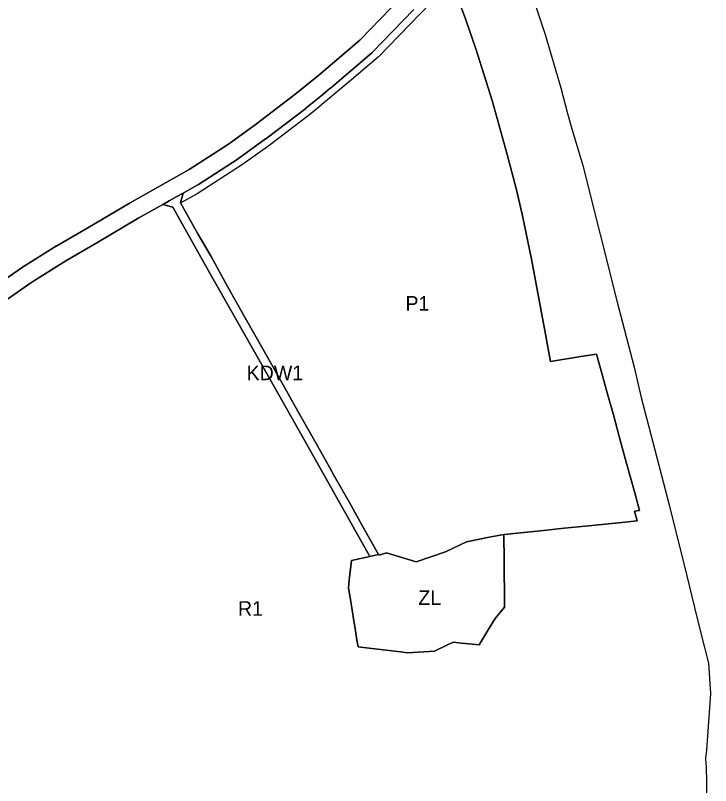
# Model space of a CAD drawing. Extents: x -284239 to -281592, y 34477 to 37267.
# Drawn here: x -282069 to -281594, y 35176 to 35702 of the extents above; entities that cross this region are included whole.
import ezdxf

# ---------------------------------------------------------------- set-up
doc = ezdxf.new("R2010")
doc.units = 0
for name, color, linetype in [('linie_rozgraniczajace', 7, 'Continuous'), ('linie_zabudowy_nieprzekraczalne', 7, 'Continuous'), ('oznaczenia_przeznaczen', 7, 'Continuous')]:
    doc.layers.add(name, color=color, linetype=linetype)

msp = doc.modelspace()

# ---------------------------------------------------------------- linework, layer by layer
at = {"layer": 'linie_rozgraniczajace'}
for points in [[(-282081.274, 35503.422), (-282058.185, 35519.415), (-282034.413, 35534.266), (-282013.182, 35546.642), (-281984.356, 35563.641), (-281967.979, 35572.857), (-281961.176, 35570.948), (-281936.796, 35527.467), (-281896.849, 35457.016), (-281862.895, 35396.825), (-281826.545, 35332.455), (-281839.226, 35329.743), (-281840.668, 35316.19), (-281841.216, 35310.682), (-281839.947, 35302.953), (-281837.553, 35288.333), (-281836.717, 35283.171), (-281835.477, 35275.298), (-281834.669, 35270.569), (-281825.269, 35269.473), (-281805.803, 35267.138), (-281800.872, 35266.474), (-281782.474, 35267.628), (-281773.563, 35271.924), (-281769.584, 35273.828), (-281763.989, 35273.251), (-281752.022, 35272.068), (-281745.735, 35282.162), (-281741.035, 35289.919), (-281734.748, 35297.763), (-281734.719, 35308.519), (-281734.921, 35321.005), (-281734.95, 35331.704), (-281735.094, 35345.114), (-281735.054, 35347.426), (-281734.928, 35347.451), (-281734.685, 35347.495), (-281728.31, 35348.135), (-281710.06, 35349.961), (-281693.834, 35351.627), (-281679.552, 35353.055), (-281665.806, 35354.463), (-281652.258, 35355.832), (-281643.986, 35356.685), (-281645.759, 35363.3), (-281642.471, 35363.873), (-281645.698, 35375.787), (-281651.448, 35396.844), (-281656.205, 35414.425), (-281660.218, 35429.193), (-281664.396, 35444.292), (-281667.83, 35456.744), (-281671.76, 35470.685), (-281682.433, 35468.948), (-281703.158, 35465.597), (-281705.95, 35480.462), (-281705.915, 35480.539), (-281716.102, 35535.44), (-281722.584, 35566.198), (-281726.685, 35583.661), (-281732.771, 35607.076), (-281743.089, 35643.787), (-281754.334, 35679.242), (-281761.081, 35699.019), (-281772.677, 35730.51)], [(-281772.677, 35730.51), (-281761.081, 35699.019), (-281754.334, 35679.242), (-281743.089, 35643.787), (-281732.771, 35607.076), (-281726.685, 35583.661), (-281722.584, 35566.198), (-281716.102, 35535.44), (-281705.915, 35480.539), (-281705.95, 35480.462), (-281703.158, 35465.597), (-281682.433, 35468.948), (-281671.76, 35470.685), (-281667.83, 35456.744), (-281664.396, 35444.292), (-281660.218, 35429.193), (-281656.205, 35414.425), (-281651.448, 35396.844), (-281645.698, 35375.787), (-281642.471, 35363.873), (-281645.759, 35363.3), (-281643.986, 35356.685), (-281652.258, 35355.832), (-281665.806, 35354.463), (-281679.552, 35353.055), (-281693.834, 35351.627), (-281710.06, 35349.961), (-281728.31, 35348.135), (-281734.685, 35347.495), (-281734.928, 35347.451), (-281735.054, 35347.426), (-281745.063, 35345.506), (-281760.618, 35342.445), (-281775.014, 35335.578), (-281794.92, 35328.736), (-281815.223, 35334.833), (-281820.353, 35333.261), (-281820.615, 35333.723), (-281831.895, 35353.656), (-281840.541, 35369.169), (-281850.924, 35387.495), (-281854.151, 35393.451), (-281862.383, 35407.889), (-281874.669, 35429.69), (-281886.872, 35451.325), (-281899.49, 35473.705), (-281911.776, 35495.506), (-281923.814, 35516.81), (-281935.107, 35537.205), (-281944.084, 35552.8), (-281950.455, 35564.218), (-281955.98, 35573.873), (-281954.106, 35580.665), (-281944.04, 35586.33), (-281943.937, 35586.407), (-281943.735, 35586.513), (-281916.576, 35603.993), (-281916.431, 35604.11), (-281916.29, 35604.189), (-281897.842, 35617.626), (-281897.779, 35617.68), (-281897.738, 35617.704), (-281870.465, 35638.486), (-281870.349, 35638.587), (-281870.299, 35638.618), (-281860.184, 35646.906), (-281853.9, 35652.055), (-281853.833, 35652.113), (-281825.411, 35676.204), (-281825.049, 35676.538), (-281825.014, 35676.589), (-281824.966, 35676.622), (-281796.575, 35706.151)], [(-281717.71, 35721.95), (-281706.88, 35688.94)], [(-281805.204, 35714.49), (-281833.404, 35685.16), (-281861.545, 35661.305), (-281877.822, 35647.966), (-281904.96, 35627.288), (-281923.215, 35613.99), (-281950.08, 35596.7), (-281990.294, 35574.069), (-281990.325, 35574.045), (-281990.399, 35574.008), (-282019.254, 35556.992), (-282040.535, 35544.587), (-282040.59, 35544.545), (-282040.693, 35544.492), (-282064.664, 35529.517), (-282064.771, 35529.432), (-282064.901, 35529.361), (-282088.246, 35513.191)], [(-282088.246, 35513.191), (-282064.901, 35529.361), (-282064.771, 35529.432), (-282064.664, 35529.517), (-282040.693, 35544.492), (-282040.59, 35544.545), (-282040.535, 35544.587), (-282019.254, 35556.992), (-281990.399, 35574.008), (-281990.325, 35574.045), (-281990.294, 35574.069), (-281950.08, 35596.7), (-281923.215, 35613.99), (-281904.96, 35627.288), (-281877.822, 35647.966), (-281861.545, 35661.305), (-281833.404, 35685.16), (-281805.204, 35714.49)], [(-281796.575, 35706.151), (-281824.966, 35676.622), (-281825.014, 35676.589), (-281825.049, 35676.538), (-281825.411, 35676.204), (-281853.833, 35652.113), (-281853.9, 35652.055), (-281860.184, 35646.906), (-281870.299, 35638.618), (-281870.349, 35638.587), (-281870.465, 35638.486), (-281897.738, 35617.704), (-281897.779, 35617.68), (-281897.842, 35617.626), (-281916.29, 35604.189), (-281916.431, 35604.11), (-281916.576, 35603.993), (-281943.735, 35586.513), (-281943.937, 35586.407)], [(-281706.88, 35688.94), (-281696.23, 35652.6), (-281691.61, 35635.02), (-281689, 35626.09), (-281681.08, 35599.44), (-281657.57, 35506.12), (-281656.02, 35500), (-281654.02, 35492.13), (-281646.16, 35461.82), (-281641.29, 35441.07), (-281634.68, 35415.65), (-281622.07, 35367.78), (-281610.04, 35319.12), (-281604.82, 35297.53), (-281600, 35278.22), (-281595.3, 35259.4), (-281593.85, 35238.77), (-281596.54, 35200.03), (-281597.17, 35196.52), (-281597.31, 35194.9), (-281597.17, 35190.8), (-281596.89, 35188.44), (-281596.74, 35178.24), (-281596.78, 35160.96)], [(-281943.937, 35586.407), (-281944.04, 35586.33), (-281954.106, 35580.665), (-281958.463, 35578.213), (-281963.622, 35575.31), (-281967.979, 35572.857), (-281984.356, 35563.641), (-282013.182, 35546.642), (-282034.413, 35534.266), (-282058.185, 35519.415), (-282081.274, 35503.422)]]:
    msp.add_lwpolyline(points, dxfattribs=at)
for points in [[(-281967.979, 35572.857), (-281963.622, 35575.31), (-281958.463, 35578.213), (-281954.106, 35580.665), (-281955.98, 35573.873), (-281950.455, 35564.218), (-281944.084, 35552.8), (-281935.107, 35537.205), (-281923.814, 35516.81), (-281911.776, 35495.506), (-281899.49, 35473.705), (-281886.872, 35451.325), (-281874.669, 35429.69), (-281862.383, 35407.889), (-281854.151, 35393.451), (-281850.924, 35387.495), (-281840.541, 35369.169), (-281831.895, 35353.656), (-281820.615, 35333.723), (-281826.545, 35332.455), (-281862.895, 35396.825), (-281896.849, 35457.016), (-281936.796, 35527.467), (-281961.176, 35570.948)], [(-281841.216, 35310.682), (-281840.668, 35316.19), (-281839.226, 35329.743), (-281826.545, 35332.455), (-281820.615, 35333.723), (-281820.353, 35333.261), (-281815.223, 35334.833), (-281794.92, 35328.736), (-281775.014, 35335.578), (-281760.618, 35342.445), (-281745.063, 35345.506), (-281735.054, 35347.426), (-281735.094, 35345.114), (-281734.95, 35331.704), (-281734.921, 35321.005), (-281734.719, 35308.519), (-281734.748, 35297.763), (-281741.035, 35289.919), (-281745.735, 35282.162), (-281752.022, 35272.068), (-281763.989, 35273.251), (-281769.584, 35273.828), (-281773.563, 35271.924), (-281782.474, 35267.628), (-281800.872, 35266.474), (-281805.803, 35267.138), (-281825.269, 35269.473), (-281834.669, 35270.569), (-281835.477, 35275.298), (-281836.717, 35283.171), (-281837.553, 35288.333), (-281839.947, 35302.953)]]:
    msp.add_lwpolyline(points, close=True, dxfattribs=at)
at = {"layer": 'linie_zabudowy_nieprzekraczalne'}
msp.add_lwpolyline([(-281770.788, 35725.479), (-281820.662, 35673.819), (-281838.919, 35658.209), (-281866.832, 35634.991), (-281894.746, 35613.56), (-281913.531, 35600.066), (-281944.487, 35580.222), (-281955.865, 35573.872)], dxfattribs=at)

# ---------------------------------------------------------------- texts
at = {"layer": 'oznaczenia_przeznaczen'}
for s, p in [('P1', (-281802.313, 35500.265)), ('KDW1', (-281910.819, 35452.819)), ('ZL', (-281793.519, 35299.332)), ('R1', (-281916.689, 35291.843))]:
    msp.add_text(s, height=10, dxfattribs=at).set_placement(p)

doc.saveas('drawing.dxf')
